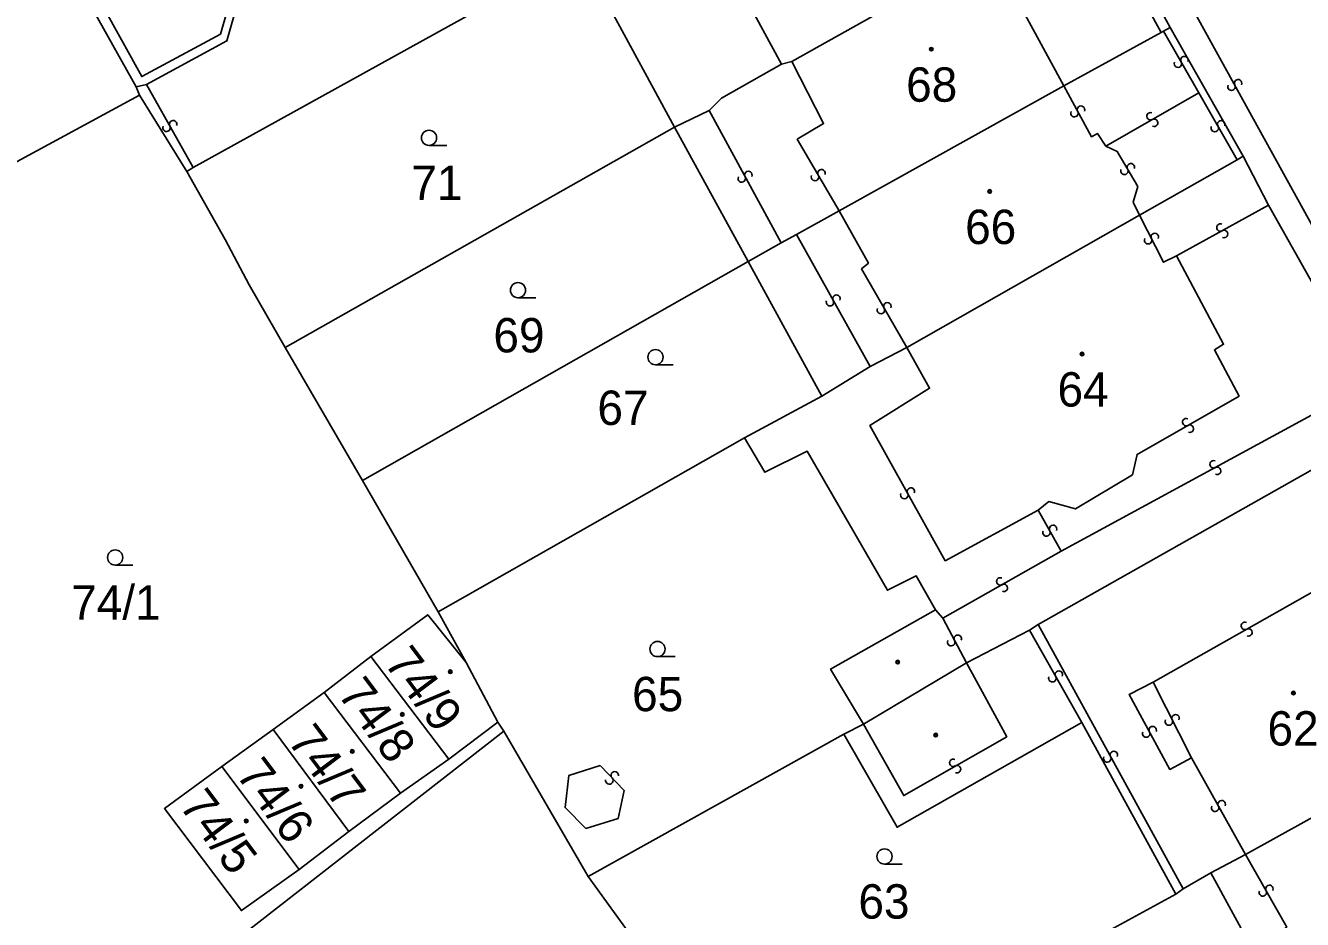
# Model space of a CAD drawing. Extents: x -600391 to -599491, y -1160176 to -1159402.
# Drawn here: x -600245.5 to -600182.3, y -1160022.8 to -1159978.6 of the extents above; entities that cross this region are included whole.
import ezdxf

# ---------------------------------------------------------------- set-up
doc = ezdxf.new("R2010")
doc.units = 0
for name, color, linetype in [('Level 1', 7, 'Continuous'), ('Level 13', 7, 'Continuous'), ('Level 3', 7, 'Continuous'), ('Level 4', 7, 'Continuous'), ('Level 5', 7, 'Continuous')]:
    doc.layers.add(name, color=color, linetype=linetype)

msp = doc.modelspace()

# ---------------------------------------------------------------- linework, layer by layer
at = {"layer": 'Level 1'}
for points in [[(-600240, -1159981.63), (-600255.84, -1159953.35)], [(-600232.09, -1159967.42), (-600235.51, -1159979.36), (-600239.49, -1159981.51)], [(-600192.48, -1159972.06), (-600188.85, -1159978.7)], [(-600218.03, -1159975.02), (-600237.17, -1159985.63)], [(-600218.03, -1159975.02), (-600213.37, -1159983.63)], [(-600197.76, -1159974.87), (-600207.56, -1159980.38)], [(-600189.3, -1159978.95), (-600194.11, -1159981.59)], [(-600189.18, -1159978.88), (-600189.3, -1159978.95)], [(-600188.85, -1159978.7), (-600189.18, -1159978.88)], [(-600188.85, -1159978.7), (-600185.25, -1159985.07)], [(-600207.56, -1159980.38), (-600208.08, -1159980.52)], [(-600208.08, -1159980.52), (-600211.04, -1159982.19), (-600211.66, -1159982.8)], [(-600239.49, -1159981.51), (-600240, -1159981.63)], [(-600240, -1159981.63), (-600239.83, -1159982.05)], [(-600194.11, -1159981.59), (-600205.22, -1159987.77)], [(-600239.83, -1159982.05), (-600250.4, -1159987.77)], [(-600239.83, -1159982.05), (-600237.49, -1159985.82)], [(-600211.66, -1159982.8), (-600213.37, -1159983.63)], [(-600213.37, -1159983.63), (-600232.62, -1159994.53)], [(-600213.37, -1159983.63), (-600209.73, -1159990.27)], [(-600185.54, -1159985.24), (-600190.37, -1159987.98)], [(-600185.25, -1159985.07), (-600185.54, -1159985.24)], [(-600185.25, -1159985.07), (-600184, -1159987.49)], [(-600237.17, -1159985.63), (-600237.49, -1159985.82)], [(-600237.49, -1159985.82), (-600235.6, -1159989.18), (-600234.4, -1159991.43), (-600232.62, -1159994.53)], [(-600205.22, -1159987.77), (-600207.34, -1159988.93)], [(-600190.37, -1159987.98), (-600201.88, -1159994.52)], [(-600184, -1159987.49), (-600179.01, -1159996.32)], [(-600207.34, -1159988.93), (-600208.09, -1159989.35)], [(-600208.09, -1159989.35), (-600209.73, -1159990.27)], [(-600209.73, -1159990.27), (-600228.8, -1160001.11)], [(-600209.73, -1159990.27), (-600206.08, -1159996.93)], [(-600232.62, -1159994.53), (-600228.8, -1160001.11)], [(-600201.88, -1159994.52), (-600203.69, -1159995.47)], [(-600203.69, -1159995.47), (-600206.08, -1159996.93)], [(-600206.08, -1159996.93), (-600209.91, -1159999)], [(-600177.88, -1159998.33), (-600195.39, -1160008.23)], [(-600209.91, -1159999), (-600225.05, -1160007.61)], [(-600209.91, -1159999), (-600208.9, -1160000.7), (-600206.8, -1159999.66), (-600202.84, -1160006.54), (-600201.42, -1160005.82), (-600200.46, -1160007.51)], [(-600228.8, -1160001.11), (-600225.05, -1160007.61)], [(-600225.05, -1160007.61), (-600223.68, -1160010.11)], [(-600200.46, -1160007.51), (-600205.65, -1160010.44), (-600204.03, -1160013.16)], [(-600223.68, -1160010.11), (-600225.57, -1160007.75), (-600228.38, -1160009.82)], [(-600195.39, -1160008.23), (-600195.82, -1160008.51)], [(-600195.82, -1160008.51), (-600198.93, -1160010.13)], [(-600228.38, -1160009.82), (-600230.69, -1160011.59)], [(-600228.38, -1160009.82), (-600224.53, -1160014.89)], [(-600223.68, -1160010.11), (-600222.11, -1160013.06)], [(-600198.93, -1160010.13), (-600204.03, -1160013.16)], [(-600230.69, -1160011.59), (-600233.22, -1160013.43)], [(-600230.69, -1160011.59), (-600226.92, -1160016.58)], [(-600224.53, -1160014.89), (-600222.11, -1160013.06)], [(-600222.11, -1160013.06), (-600221.81, -1160013.5)], [(-600205, -1160013.66), (-600202.36, -1160018.26), (-600193.23, -1160013.08)], [(-600204.03, -1160013.16), (-600205, -1160013.66)], [(-600193.23, -1160013.08), (-600188.58, -1160021.57)], [(-600221.81, -1160013.5), (-600254.43, -1160038.93)], [(-600233.22, -1160013.43), (-600235.75, -1160015.25)], [(-600233.22, -1160013.43), (-600229.48, -1160018.47)], [(-600217.64, -1160020.7), (-600221.81, -1160013.5)], [(-600205, -1160013.66), (-600217.64, -1160020.7)], [(-600175.74, -1160014.4), (-600185.13, -1160019.6)], [(-600226.92, -1160016.58), (-600224.53, -1160014.89)], [(-600235.75, -1160015.25), (-600238.6, -1160017.34), (-600234.79, -1160022.38), (-600231.94, -1160020.35)], [(-600235.75, -1160015.25), (-600231.94, -1160020.35)], [(-600229.48, -1160018.47), (-600226.92, -1160016.58)], [(-600231.94, -1160020.35), (-600229.48, -1160018.47)], [(-600185.13, -1160019.6), (-600186.85, -1160020.51)], [(-600212.97, -1160027.15), (-600217.64, -1160020.7)], [(-600186.85, -1160020.51), (-600188.22, -1160021.31)], [(-600183.73, -1160026.23), (-600186.85, -1160020.51)], [(-600188.22, -1160021.31), (-600188.58, -1160021.57)], [(-600188.58, -1160021.57), (-600195.46, -1160025.33)]]:
    msp.add_lwpolyline(points, dxfattribs=at)
at = {"layer": 'Level 13'}
for centre, start, end in [((-600188.471, -1159980.49), 157.07714, 29.17513), ((-600188.15, -1159980.309), 336.86268, 209.45268), ((-600185.822, -1159981.628), 156.0389, 28.6289), ((-600185.498, -1159981.452), 336.25336, 208.35135), ((-600193.592, -1159982.937), 155.60856, 28.19856), ((-600193.267, -1159982.764), 335.82301, 207.92101), ((-600189.83, -1159983.089), 67.22481, 299.32281), ((-600238.491, -1159983.66), 156.54244, 29.13244), ((-600238.168, -1159983.481), 336.75689, 208.85489), ((-600189.649, -1159983.41), 247.01036, 119.60036), ((-600186.65, -1159983.671), 157.01488, 29.60488), ((-600186.329, -1159983.49), 337.22934, 209.32734), ((-600190.8, -1159985.608), 337.64976, 209.74776), ((-600210.043, -1159986.167), 155.9648, 28.0628), ((-600209.718, -1159985.993), 335.75035, 208.34035), ((-600206.42, -1159986.092), 157.80998, 29.90798), ((-600206.101, -1159985.907), 337.59552, 210.18552), ((-600191.119, -1159985.792), 157.4353, 30.0253), ((-600186.368, -1159988.588), 66.04153, 298.63153), ((-600189.945, -1159989.222), 154.01765, 26.60765), ((-600189.615, -1159989.058), 334.23211, 206.33011), ((-600186.192, -1159988.912), 246.25599, 118.35398), ((-600205.682, -1159992.288), 156.53879, 28.63679), ((-600205.359, -1159992.111), 336.32434, 208.91434), ((-600202.84, -1159992.489), 337.15696, 209.74696), ((-600203.161, -1159992.671), 157.37141, 29.46941), ((-600188.061, -1159998.22), 66.98878, 299.57878), ((-600187.88, -1159998.541), 247.20324, 119.30124), ((-600186.707, -1160000.307), 65.93309, 298.03109), ((-600186.533, -1160000.632), 245.71863, 118.30863), ((-600202.002, -1160001.828), 156.51452, 28.61252), ((-600201.679, -1160001.651), 336.30007, 208.89007), ((-600194.971, -1160003.68), 156.56934, 29.15934), ((-600194.648, -1160003.501), 336.7838, 208.88179), ((-600197.259, -1160006.098), 66.75833, 298.85633), ((-600197.08, -1160006.421), 246.54388, 119.13388), ((-600185.159, -1160008.299), 66.85066, 298.94866), ((-600199.357, -1160008.935), 334.94872, 207.53872), ((-600184.98, -1160008.621), 246.6362, 119.2262), ((-600199.684, -1160009.104), 155.16318, 27.26117), ((-600194.359, -1160010.71), 336.70022, 209.29022), ((-600194.681, -1160010.889), 156.91468, 29.01268), ((-600188.586, -1160012.867), 334.08982, 206.67982), ((-600189.718, -1160013.453), 335.60618, 208.19618), ((-600188.915, -1160013.032), 154.30428, 26.40228), ((-600190.043, -1160013.626), 155.82064, 27.91863), ((-600191.638, -1160014.682), 335.88829, 208.47829), ((-600199.581, -1160015.07), 66.91528, 299.50528), ((-600199.4, -1160015.391), 247.12974, 119.22773), ((-600191.963, -1160014.857), 156.10275, 28.20075), ((-600216.594, -1160015.946), 170.74965, 43.33965), ((-600216.325, -1160015.694), 350.96411, 223.0621), ((-600186.309, -1160017.121), 336.34502, 208.93502), ((-600186.632, -1160017.298), 156.55947, 28.65747), ((-600184.271, -1160021.489), 156.91152, 29.00951), ((-600183.949, -1160021.31), 336.69706, 209.28706)]:
    msp.add_arc(centre, 0.184, start, end, dxfattribs=at)
at = {"layer": 'Level 3'}
for points in [[(-600216.41, -1159929.12), (-600215.68, -1159929.11), (-600215.05, -1159929.27), (-600214.48, -1159929.6), (-600214.01, -1159930.08), (-600213.7, -1159930.71), (-600157.62, -1160032.38), (-600157.61, -1160032.9), (-600157.65, -1160033.43)], [(-600232.58, -1159967.72), (-600235.83, -1159979.02), (-600239.72, -1159981.13), (-600255.07, -1159953.42), (-600251.39, -1159951.35)], [(-600208.08, -1159980.52), (-600210.75, -1159975.58), (-600209.99, -1159975.07), (-600211.93, -1159971.4)], [(-600192.94, -1159972.29), (-600189.3, -1159978.95)], [(-600197.76, -1159974.87), (-600194.11, -1159981.59)], [(-600187.44, -1159981.93), (-600189.18, -1159978.88)], [(-600205.22, -1159987.77), (-600207.3, -1159984.23), (-600206, -1159983.45), (-600207.56, -1159980.38)], [(-600239.49, -1159981.51), (-600237.17, -1159985.63)], [(-600194.11, -1159981.59), (-600192.75, -1159984.1), (-600192.45, -1159983.94), (-600192.04, -1159984.57)], [(-600192.04, -1159984.57), (-600187.44, -1159981.93)], [(-600187.44, -1159981.93), (-600185.54, -1159985.24)], [(-600208.09, -1159989.35), (-600211.66, -1159982.8)], [(-600192.04, -1159984.57), (-600191.47, -1159984.83), (-600190.46, -1159986.56), (-600190.68, -1159987.34), (-600190.37, -1159987.98)], [(-600201.88, -1159994.52), (-600204.12, -1159990.64), (-600203.78, -1159990.35), (-600205.22, -1159987.77)], [(-600190.37, -1159987.98), (-600189.19, -1159990.31), (-600188.55, -1159990)], [(-600184, -1159987.49), (-600188.55, -1159990)], [(-600203.69, -1159995.47), (-600207.34, -1159988.93)], [(-600188.55, -1159990), (-600186.21, -1159994.37), (-600186.67, -1159994.65), (-600185.45, -1159996.93), (-600190.49, -1159999.82), (-600190.71, -1160000.82), (-600193.54, -1160002.51), (-600194.86, -1160002.15), (-600195.39, -1160002.57)], [(-600195.39, -1160002.57), (-600199.98, -1160005.08), (-600203.71, -1159998.39), (-600200.75, -1159996.54), (-600201.88, -1159994.52)], [(-600194.24, -1160004.61), (-600179.01, -1159996.32)], [(-600195.39, -1160002.57), (-600194.24, -1160004.61)], [(-600200.1, -1160007.91), (-600194.24, -1160004.61)], [(-600189.7, -1160011.08), (-600180.43, -1160005.84)], [(-600200.46, -1160007.51), (-600200.1, -1160007.91)], [(-600198.93, -1160010.13), (-600200.1, -1160007.91)], [(-600188.22, -1160021.31), (-600195.39, -1160008.23)], [(-600193.23, -1160013.08), (-600195.82, -1160008.51)], [(-600198.93, -1160010.13), (-600196.94, -1160013.78), (-600202.03, -1160016.69), (-600204.03, -1160013.16)], [(-600187.8, -1160014.82), (-600188.87, -1160015.4), (-600190.88, -1160011.69), (-600189.7, -1160011.08)], [(-600187.8, -1160014.82), (-600189.7, -1160011.08)], [(-600217.05, -1160015.2), (-600215.86, -1160016.45), (-600216.15, -1160017.82), (-600217.76, -1160018.32), (-600218.78, -1160017.29), (-600218.59, -1160015.7), (-600217.05, -1160015.2)], [(-600185.13, -1160019.6), (-600187.8, -1160014.82)], [(-600182.77, -1160025.77), (-600183.82, -1160023.7), (-600183.09, -1160023.2), (-600185.13, -1160019.6)]]:
    msp.add_lwpolyline(points, dxfattribs=at)
at = {"layer": 'Level 5'}
for p, q in [((-600225.51, -1159984.53), (-600224.635, -1159984.53)), ((-600221.11, -1159992.07), (-600220.235, -1159992.07)), ((-600214.31, -1159995.38), (-600213.435, -1159995.38)), ((-600241.03, -1160005.29), (-600240.155, -1160005.29)), ((-600214.21, -1160009.82), (-600213.335, -1160009.82)), ((-600202.98, -1160020.08), (-600202.105, -1160020.08))]:
    msp.add_line(p, q, dxfattribs=at)
for centre, radius in [((-600200.67, -1159979.77), 0.09), ((-600200.67, -1159979.77), 0.0521), ((-600225.51, -1159984.155), 0.375), ((-600197.78, -1159986.81), 0.09), ((-600197.78, -1159986.81), 0.0521), ((-600221.11, -1159991.695), 0.375), ((-600214.31, -1159995.005), 0.375), ((-600193.21, -1159994.85), 0.09), ((-600193.21, -1159994.85), 0.0521), ((-600241.03, -1160004.915), 0.375), ((-600214.21, -1160009.445), 0.375), ((-600202.33, -1160010.09), 0.09), ((-600202.33, -1160010.09), 0.0521), ((-600224.46, -1160010.57), 0.09), ((-600224.46, -1160010.57), 0.0521), ((-600182.76, -1160011.62), 0.09), ((-600182.76, -1160011.62), 0.0521), ((-600226.83, -1160012.68), 0.09), ((-600226.83, -1160012.68), 0.0521), ((-600200.45, -1160013.7), 0.09), ((-600200.45, -1160013.7), 0.0521), ((-600229.31, -1160014.51), 0.09), ((-600229.31, -1160014.51), 0.0521), ((-600231.84, -1160016.23), 0.09), ((-600231.84, -1160016.23), 0.0521), ((-600234.55, -1160017.95), 0.09), ((-600234.55, -1160017.95), 0.0521), ((-600202.98, -1160019.705), 0.375)]:
    msp.add_circle(centre, radius, dxfattribs=at)

# ---------------------------------------------------------------- texts
at = {"layer": 'Level 4'}
for s, p in [('68', (-600201.914, -1159982.37)), ('71', (-600226.383, -1159987.23)), ('66', (-600198.996, -1159989.41)), ('69', (-600222.326, -1159994.77)), ('64', (-600194.426, -1159997.45)), ('67', (-600217.181, -1159998.36)), ('74/1', (-600243.208, -1160007.99)), ('65', (-600215.467, -1160012.52)), ('62', (-600184.041, -1160014.22)), ('63', (-600204.273, -1160022.78))]:
    msp.add_text(s, height=1.7, dxfattribs=at).set_placement(p)
for s, p in [('74/9', (-600227.772, -1160010.142)), ('74/8', (-600230.073, -1160011.678)), ('74/7', (-600232.551, -1160014.001)), ('74/6', (-600235.102, -1160015.662)), ('74/5', (-600237.907, -1160017.199))]:
    msp.add_text(s, height=1.7, rotation=306.9, dxfattribs=at).set_placement(p)

doc.saveas('drawing.dxf')
